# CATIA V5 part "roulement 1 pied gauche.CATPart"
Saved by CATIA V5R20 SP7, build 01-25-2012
Part number: roulement 1 pied gauche
Bounding box of the stored display mesh (mm): x 17.514 to 31.522, y -79 to -65, z 35.293 to 46.556
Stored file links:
  F:\Travaux\Modélisations\CFAO_2011\CFAO_2011_MMS\CFAO_2011_MMS_DONE\CFAO_2011_MMS_jboiteux\Catia\roulement 1 pied gauche.CATPart
  U:\finthinkmotion\stepper.CATProduct
  F:\Travaux\Modélisations\CFAO_2011\CFAO_2011_MMS\CFAO_2011_MMS_DONE\CFAO_2011_MMS_jboiteux\Catia\entretoise pied gauche.CATPart
  F:\Travaux\Modélisations\CFAO_2011\CFAO_2011_MMS\CFAO_2011_MMS_DONE\CFAO_2011_MMS_jboiteux\Catia\rondelle 1 pied gauche.CATPart
  F:\Travaux\Modélisations\CFAO_2011\CFAO_2011_MMS\CFAO_2011_MMS_DONE\CFAO_2011_MMS_jboiteux\Catia\Part1.CATPart
  F:\Travaux\Modélisations\CFAO_2011\CFAO_2011_MMS\CFAO_2011_MMS_DONE\CFAO_2011_MMS_jboiteux\Catia\bati.CATPart
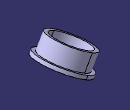
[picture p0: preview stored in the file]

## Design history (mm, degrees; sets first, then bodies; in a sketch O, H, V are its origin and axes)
Parameters
  rayontube = 9 mm {= External.royontubebati}
External parameters (linked from other documents)
  External.royontubebati = 9 mm
Set1
  DatumSurface1 to DatumSurface3: linked copy from another document
  Point1: linked copy from another document
Body1 (main body)
  Sketch1 on face of DatumSurface3, origin (-10.4328, 0, 18.0701), H (0, 1, 0), V (0.866, 0, 0.5)
    projected circle E1 centre (-72, 41.4454) radius 7 from edge of DatumSurface3
    projected circle E2 centre (-72, 41.4454) radius 5 from edge of DatumSurface3
  Pad1: profile Sketch1, direction (-0.5, 0, 0.866), length 1
  Sketch2 on end face of Pad1, origin (-10.9328, 0, 18.9361), H (0, -1, 0), V (0.866, 0, 0.5)
    projected circle E1 centre (72, 41.4454) radius 5 from edge [face of Pad1 from Sketch1.E2 | end face of Pad1]
    circle A1 centre (72, 41.4454) radius 6
    point P1 (72, 41.4454)
    reference projected point E2 (72, 41.4454) from Point1
    radius A1 = 6 {= rayontube *5/9+1mm}
    coincidence: E2 P1
  Pad2: profile Sketch2, direction (-0.5, 0, 0.866), length 4.5 {= rayontube /2}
